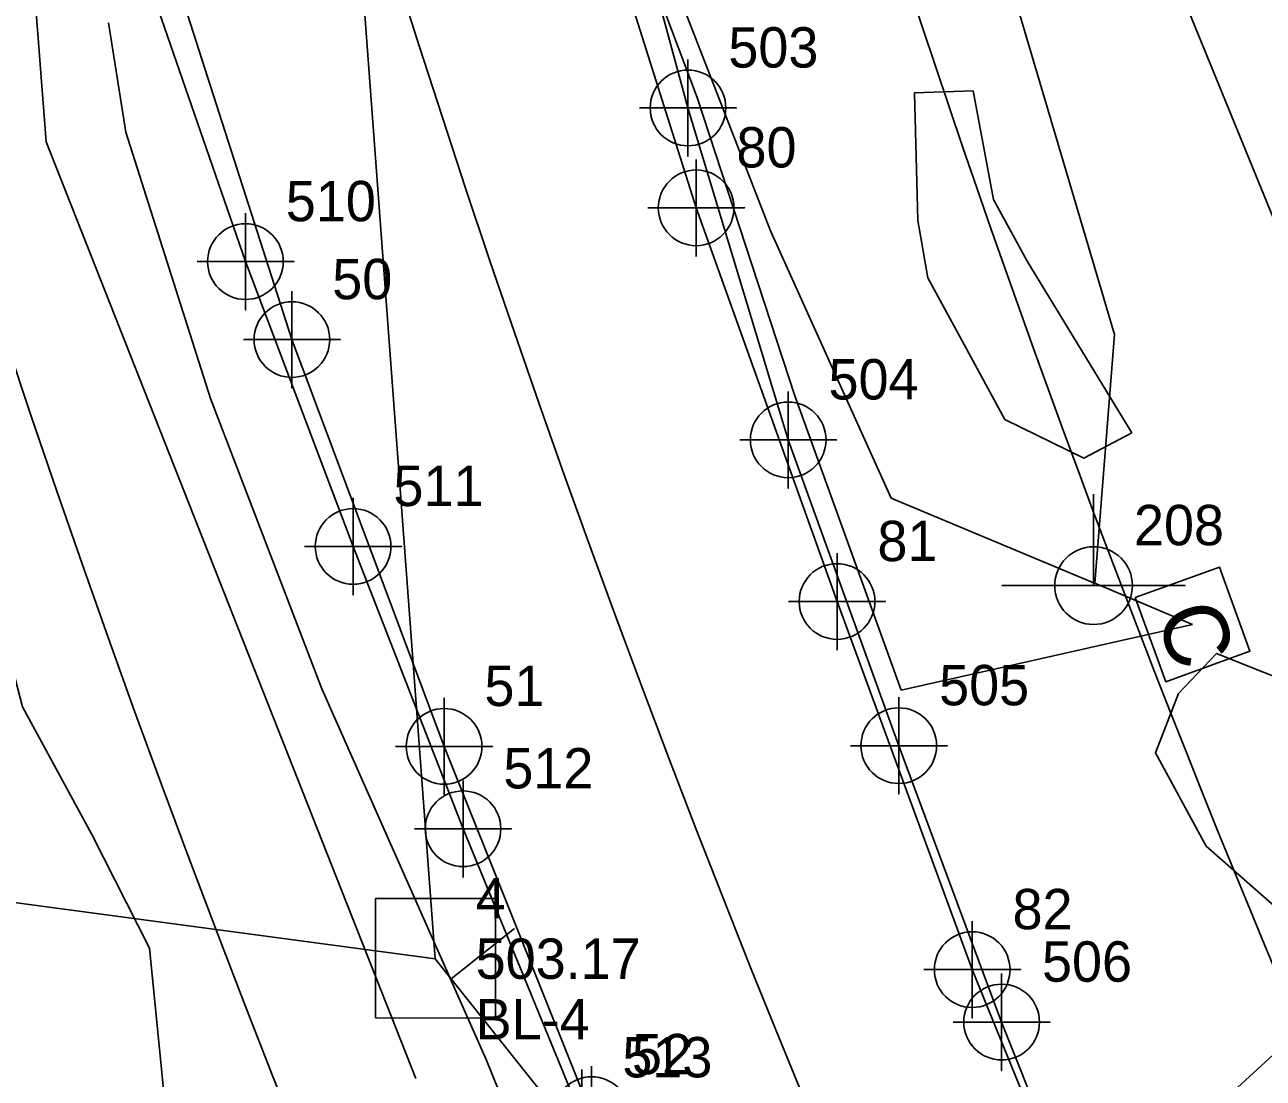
# Model space of a CAD drawing. Extents: x 1534145 to 1537876, y 509021 to 513201.
# Drawn here: x 1536040.8 to 1536117.6, y 511790.2 to 511855.4 of the extents above; entities that cross this region are included whole.
import ezdxf

# ---------------------------------------------------------------- set-up
doc = ezdxf.new("R2010")
doc.units = 0
for name, color, linetype in [('CTL Supplemental Horizontal and Vertical CELL', 7, 'Continuous'), ('CTL Supplemental Horizontal and Vertical Cogo Comment', 7, 'Continuous'), ('CTL Supplemental Horizontal and Vertical Cogo Elevation', 7, 'Continuous'), ('CTL Supplemental Horizontal and Vertical Cogo Number', 7, 'Continuous'), ('Exist Guardrail', 7, 'Continuous'), ('Exist Guardrail Cogo Number', 7, 'Continuous'), ('Exist Guardrail Cogo Point CELL', 7, 'Continuous'), ('Exist Horizontal Alignment', 7, 'Continuous'), ('Exist Horizontal Baseline Alignment', 7, 'Continuous'), ('Exist Horizontal Baseline Alignment Station Label', 7, 'Continuous'), ('Exist Horizontal Baseline Alignment Tick small', 7, 'Continuous'), ('Exist Right of Way Line', 7, 'Continuous'), ('Exist Roads EOP', 7, 'Continuous'), ('Exist Roads EOP Cogo Number', 7, 'Continuous'), ('Exist Roads EOP Cogo Point CELL', 7, 'Continuous'), ('Exist Structure Major Bridge Seat Top Elevation', 7, 'Continuous'), ('Exist Utilities Telephone Joint Use Power CELL', 7, 'Continuous'), ('Exist Utilities Telephone Joint Use Power Cogo Number', 7, 'Continuous'), ('Exist Utilities Telephone UG Cable', 7, 'Continuous'), ('Exist Utilities Telephone UG FO SUE', 7, 'Continuous'), ('Exist Utilities TV Pedestal CELL', 7, 'Continuous'), ('Exist Utilities TV UG Cable', 7, 'Continuous'), ('Exist Utilities Water UG Line SUE', 7, 'Continuous'), ('Exist Vegetation Hedge Row', 7, 'Continuous'), ('Exist Vegetation Woods Line', 7, 'Continuous')]:
    doc.layers.add(name, color=color, linetype=linetype)

# ---------------------------------------------------------------- blocks, each defined once
blk = doc.blocks.new('EXIST UTILITIES TELEPHONE JOINT USE POWER')
at = {"layer": 'Exist Utilities Telephone Joint Use Power CELL'}
blk.add_line((0, 0), (0, 0), dxfattribs=at)
blk.add_lwpolyline([(-0.1135, 0), (0.11325, 0), (0, 0), (0, 0.1135)], dxfattribs=at)
blk.add_circle((0, 0), 0.04813, dxfattribs=at)
blk = doc.blocks.new('CTL SUPPLEMENTAL HORIZONTAL AND VERTICAL')
at = {"layer": 'CTL Supplemental Horizontal and Vertical CELL'}
blk.add_line((0, 0), (0, 0), dxfattribs=at)
blk.add_lwpolyline([(-0.1043, 0.0004), (0.0005, 0.1052), (0.1055, 0.0002), (0.0007, -0.1047)], close=True, dxfattribs=at)

msp = doc.modelspace()

# ---------------------------------------------------------------- linework, layer by layer
at = {"layer": 'Exist Guardrail'}
for points in [[(1536074.853, 511872.535), (1536075.971, 511871.123), (1536078.13, 511864.339), (1536081.932, 511850.29), (1536088.139, 511829.732), (1536094.992, 511810.789), (1536101.363, 511793.669), (1536106.713, 511780.223)], [(1536048.092, 511860.888), (1536048.2, 511859.044), (1536054.518, 511840.772), (1536061.186, 511823.13), (1536067.995, 511805.641), (1536075.366, 511787.741), (1536083.083, 511770.088)]]:
    msp.add_lwpolyline(points, dxfattribs=at)
at = {"layer": 'Exist Guardrail Cogo Point CELL'}
for points in [[(1536081.932, 511853.29), (1536081.932, 511847.29), (1536081.932, 511850.29), (1536084.932, 511850.29), (1536078.932, 511850.29)], [(1536054.518, 511843.772), (1536054.518, 511837.772), (1536054.518, 511840.772), (1536057.518, 511840.772), (1536051.518, 511840.772)], [(1536088.139, 511832.732), (1536088.139, 511826.732), (1536088.139, 511829.732), (1536091.139, 511829.732), (1536085.139, 511829.732)], [(1536061.186, 511826.13), (1536061.186, 511820.13), (1536061.186, 511823.13), (1536064.186, 511823.13), (1536058.186, 511823.13)], [(1536094.992, 511813.789), (1536094.992, 511807.789), (1536094.992, 511810.789), (1536097.992, 511810.789), (1536091.992, 511810.789)], [(1536067.995, 511808.641), (1536067.995, 511802.641), (1536067.995, 511805.641), (1536070.995, 511805.641), (1536064.995, 511805.641)], [(1536101.363, 511796.669), (1536101.363, 511790.669), (1536101.363, 511793.669), (1536104.363, 511793.669), (1536098.363, 511793.669)], [(1536075.366, 511790.741), (1536075.366, 511784.741), (1536075.366, 511787.741), (1536078.366, 511787.741), (1536072.366, 511787.741)]]:
    msp.add_lwpolyline(points, dxfattribs=at)
for centre in [(1536081.932, 511850.29), (1536054.518, 511840.772), (1536088.139, 511829.732), (1536061.186, 511823.13), (1536094.992, 511810.789), (1536067.995, 511805.641), (1536101.363, 511793.669)]:
    msp.add_circle(centre, 2.344, dxfattribs=at)
at = {"layer": 'Exist Horizontal Alignment'}
msp.add_arc((1536874.855, 512113.154), 850, 183.46397, 223.994403, dxfattribs=at)
at = {"layer": 'Exist Horizontal Baseline Alignment'}
for p, q in [((1536014.279, 512494.062), (1536066.279, 511797.596)), ((1536066.279, 511797.596), (1536449.441, 511315.8))]:
    msp.add_line(p, q, dxfattribs=at)
at = {"layer": 'Exist Horizontal Baseline Alignment Station Label'}
msp.add_lwpolyline([(1536015.468, 511826.298), (1536028.303, 511802.669), (1536066.279, 511797.596)], dxfattribs=at)
at = {"layer": 'Exist Horizontal Baseline Alignment Tick small'}
msp.add_line((1536067.272, 511796.347), (1536071.185, 511799.459), dxfattribs=at)
at = {"layer": 'Exist Right of Way Line'}
for radius, end in [(820, 207.242925), (880, 223.994403)]:
    msp.add_arc((1536874.855, 512113.154), radius, 183.46397, end, dxfattribs=at)
at = {"layer": 'Exist Roads EOP'}
for points in [[(1536017.127, 512355.263), (1536014.258, 512300.49), (1536012.138, 512243.655), (1536010.766, 512187.002), (1536010.935, 512130.319), (1536011.885, 512103.447), (1536013.151, 512076.442), (1536015.189, 512049.652), (1536017.801, 512022.412), (1536021.134, 511995.466), (1536025.003, 511968.91), (1536024.581, 511966.831), (1536029.206, 511941.046), (1536034.764, 511914.701), (1536041.437, 511889.37), (1536049.315, 511861.119), (1536057.395, 511835.942), (1536066.823, 511810.745), (1536075.962, 511787.935), (1536078.268, 511780.03), (1536082.687, 511771.896), (1536083.544, 511771.142)], [(1536047.727, 511997.734), (1536051.294, 511973.891), (1536055.95, 511946.526), (1536061.193, 511920.283), (1536066.769, 511896.005), (1536074.658, 511868.783), (1536082.438, 511844.103), (1536091.167, 511819.718), (1536099.538, 511796.917), (1536105.626, 511781.946), (1536105.402, 511780.92)]]:
    msp.add_lwpolyline(points, dxfattribs=at)
at = {"layer": 'Exist Roads EOP Cogo Point CELL'}
for points in [[(1536082.438, 511847.103), (1536082.438, 511841.103), (1536082.438, 511844.103), (1536085.438, 511844.103), (1536079.438, 511844.103)], [(1536057.395, 511838.942), (1536057.395, 511832.942), (1536057.395, 511835.942), (1536060.395, 511835.942), (1536054.395, 511835.942)], [(1536091.167, 511822.718), (1536091.167, 511816.718), (1536091.167, 511819.718), (1536094.167, 511819.718), (1536088.167, 511819.718)], [(1536066.823, 511813.745), (1536066.823, 511807.745), (1536066.823, 511810.745), (1536069.823, 511810.745), (1536063.823, 511810.745)], [(1536099.538, 511799.917), (1536099.538, 511793.917), (1536099.538, 511796.917), (1536102.538, 511796.917), (1536096.538, 511796.917)], [(1536075.962, 511790.935), (1536075.962, 511784.935), (1536075.962, 511787.935), (1536078.962, 511787.935), (1536072.962, 511787.935)]]:
    msp.add_lwpolyline(points, dxfattribs=at)
for centre in [(1536082.438, 511844.103), (1536057.395, 511835.942), (1536091.167, 511819.718), (1536066.823, 511810.745), (1536099.538, 511796.917), (1536075.962, 511787.935)]:
    msp.add_circle(centre, 2.344, dxfattribs=at)
at = {"layer": 'Exist Structure Major Bridge Seat Top Elevation'}
msp.add_lwpolyline([(1536104.719, 511779.32), (1536145.84, 511816.961), (1536143.09, 511822.293)], dxfattribs=at)
at = {"layer": 'Exist Utilities Telephone UG Cable'}
for p, q in [((1536079.227, 511862.804), (1536087.051, 511842.686)), ((1536087.051, 511842.686), (1536094.52, 511826.11)), ((1536094.52, 511826.11), (1536107.149, 511820.843))]:
    msp.add_line(p, q, dxfattribs=at)
msp.add_lwpolyline([(1536007.514, 512112.188), (1536011.33, 512050.437), (1536011.992, 512042.854), (1536022.088, 511963.64), (1536039.724, 511880.013), (1536042.168, 511848.194), (1536065.07, 511790.175)], dxfattribs=at)
at = {"layer": 'Exist Utilities Telephone UG FO SUE'}
for p, q in [((1536101.606, 511859.015), (1536108.358, 511836.248)), ((1536046.037, 511855.556), (1536047.109, 511848.796)), ((1536047.109, 511848.796), (1536052.361, 511832.295)), ((1536108.358, 511836.248), (1536107.146, 511820.85)), ((1536052.361, 511832.295), (1536059.246, 511814.311)), ((1536059.246, 511814.311), (1536069.439, 511791.359)), ((1536069.439, 511791.359), (1536075.107, 511777.315))]:
    msp.add_line(p, q, dxfattribs=at)
at = {"layer": 'Exist Utilities TV Pedestal CELL'}
msp.add_line((1536113.19, 511818.298), (1536113.19, 511818.298), dxfattribs=at)
msp.add_lwpolyline([(1536109.635, 511819.961), (1536111.527, 511814.743), (1536116.745, 511816.635), (1536114.853, 511821.853), (1536109.635, 511819.961)], dxfattribs=at)
at = {"layer": 'Exist Utilities TV UG Cable'}
for p, q in [((1536073.935, 511873.691), (1536082.502, 511850.933)), ((1536082.502, 511850.933), (1536088.552, 511832.451)), ((1536088.552, 511832.451), (1536095.139, 511814.229)), ((1536113.19, 511818.298), (1536107.146, 511820.85)), ((1536095.139, 511814.229), (1536113.19, 511818.298))]:
    msp.add_line(p, q, dxfattribs=at)
at = {"layer": 'Exist Utilities Water UG Line SUE'}
msp.add_line((1536109.144, 511865.618), (1536126.222, 511823.792), dxfattribs=at)
at = {"layer": 'Exist Vegetation Hedge Row'}
for points in [[(1536096.165, 511843.31), (1536095.962, 511851.225), (1536099.592, 511851.34), (1536100.86, 511844.619), (1536102.94, 511840.795), (1536109.418, 511830.171), (1536106.459, 511828.587), (1536101.565, 511830.999), (1536099.07, 511835.586), (1536096.793, 511839.772), (1536096.165, 511843.31)], [(1536118.596, 511800.564), (1536114.036, 511804.574), (1536110.893, 511810.352), (1536112.319, 511814.018), (1536114.667, 511816.506), (1536120.575, 511814.143), (1536123.542, 511808.687), (1536123.513, 511798.94), (1536120.154, 511799.911), (1536118.596, 511800.564)]]:
    msp.add_lwpolyline(points, dxfattribs=at)
at = {"layer": 'Exist Vegetation Woods Line'}
msp.add_lwpolyline([(1535954.041, 511853.161), (1535966.022, 511858.509), (1535970.596, 511870.907), (1535970.151, 511875.739), (1535974.712, 511881.103), (1535988.59, 511888.028), (1536000.971, 511889.585), (1536009.774, 511882.212), (1536016.62, 511871.882), (1536024.488, 511859.378), (1536025.314, 511851.257), (1536029.328, 511842.498), (1536032.33, 511832.43), (1536038.105, 511823.163), (1536040.702, 511813.198), (1536045.004, 511805.288), (1536048.576, 511798.251), (1536049.606, 511787.843), (1536052.615, 511782.044), (1536051.189, 511773.439), (1536046.439, 511770.727), (1536040.522, 511767.509), (1536036.361, 511759.528)], dxfattribs=at)

# ---------------------------------------------------------------- block references
at = {"layer": 'CTL Supplemental Horizontal and Vertical CELL', "xscale": 50, "yscale": 49.99999999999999, "rotation": 44.99999999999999}
msp.add_blockref('CTL SUPPLEMENTAL HORIZONTAL AND VERTICAL', (1536066.279, 511797.596), dxfattribs=at)
at = {"layer": 'Exist Utilities Telephone Joint Use Power CELL', "xscale": 50, "yscale": 50}
msp.add_blockref('EXIST UTILITIES TELEPHONE JOINT USE POWER', (1536107.06, 511820.702), dxfattribs=at)

# ---------------------------------------------------------------- texts
at = {"layer": 'CTL Supplemental Horizontal and Vertical Cogo Comment'}
msp.add_text('BL-4', height=2.5, dxfattribs=at).set_placement((1536068.779, 511792.596))
at = {"layer": 'CTL Supplemental Horizontal and Vertical Cogo Elevation'}
msp.add_text('503.17', height=2.5, dxfattribs=at).set_placement((1536068.779, 511796.346))
at = {"layer": 'CTL Supplemental Horizontal and Vertical Cogo Number'}
msp.add_text('4', height=2.5, dxfattribs=at).set_placement((1536068.779, 511800.096))
at = {"layer": 'Exist Guardrail Cogo Number'}
for s, p in [('503', (1536084.432, 511852.79)), ('510', (1536057.018, 511843.273)), ('504', (1536090.639, 511832.232)), ('511', (1536063.686, 511825.63)), ('505', (1536097.492, 511813.289)), ('512', (1536070.495, 511808.141)), ('506', (1536103.863, 511796.169)), ('513', (1536077.866, 511790.242))]:
    msp.add_text(s, height=2.5, dxfattribs=at).set_placement(p)
at = {"layer": 'Exist Roads EOP Cogo Number'}
for s, p in [('80', (1536084.938, 511846.603)), ('50', (1536059.895, 511838.442)), ('81', (1536093.667, 511822.218)), ('51', (1536069.323, 511813.245)), ('82', (1536102.038, 511799.417)), ('52', (1536078.462, 511790.435))]:
    msp.add_text(s, height=2.5, dxfattribs=at).set_placement(p)
at = {"layer": 'Exist Utilities Telephone Joint Use Power Cogo Number'}
msp.add_text('208', height=2.5, dxfattribs=at).set_placement((1536109.56, 511823.203))
at = {"layer": 'Exist Utilities TV Pedestal CELL'}
msp.add_text('C', height=4, rotation=289.92909, dxfattribs=at).set_placement((1536110.864, 511818.845))

doc.saveas('drawing.dxf')
